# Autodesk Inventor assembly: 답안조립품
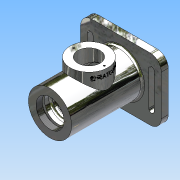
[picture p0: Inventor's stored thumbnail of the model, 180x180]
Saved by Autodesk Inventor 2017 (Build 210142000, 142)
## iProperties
Part Number: 답안조립품
Material: 일반
Document SubType Name: Assembly
Designer: user
Author: user
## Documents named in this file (2)
- C:\Users\user\Desktop\710706V1027\답안조립품.iam
- C:\Users\user\Desktop\710706V1027\본체.ipt
